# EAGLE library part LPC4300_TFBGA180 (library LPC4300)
TFBGA180 - SOT570-3 TFBGA180: thin fine-pitch ball grid array package; 180 balls body 12 x 12 x 0.8 mm; Solderland 0.4 mm diameter Grid 0.8 x 0.8 mm
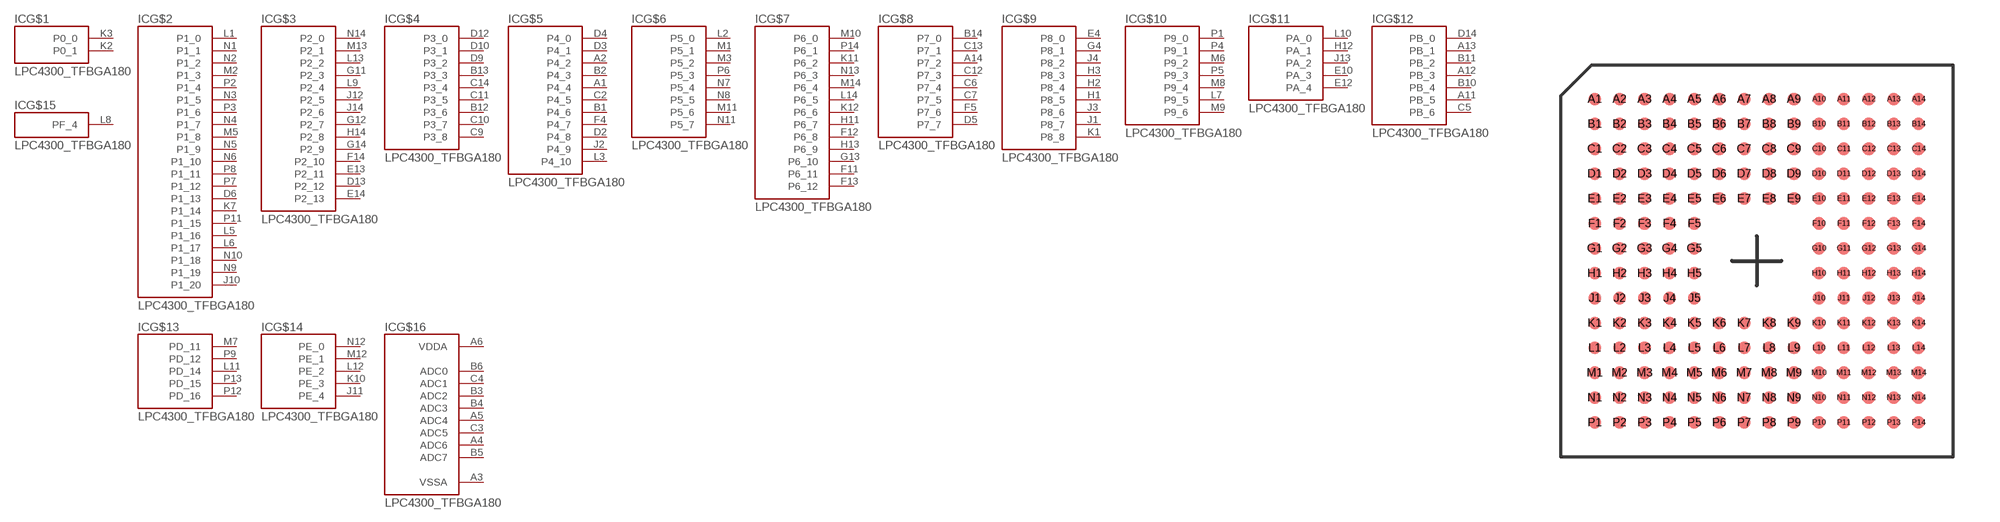
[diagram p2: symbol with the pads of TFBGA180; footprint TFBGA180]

Designator prefix IC; gates G$1=180_1_PORT0 G$2=180_2_PORT1 G$3=180_3_PORT2 G$4=180_4_PORT3 G$5=180_5_PORT4 G$6=180_6_PORT5 G$7=180_7_PORT6 G$8=180_8_PORT7 G$9=180_9_PORT8 G$10=180_10_PORT9 G$11=180_11_PORTA G$12=180_12_PORTB G$13=180_14_PORTD G$14=180_15_PORTE G$15=180_16_PORTF G$16=180_17_ANA G$17=180_18_RTC G$18=180_19_CLK G$19=180_20_DBUG G$20=180_21_I2C G$21=180_22_SUP G$22=180_23_USB

## LPC4300_TFBGA180  [TFBGA180]
A1  G$5:P4_4
A2  G$5:P4_2
A3  G$16:VSSA  sup
A4  G$16:ADC6  in
A5  G$16:ADC4  in
A6  G$16:VDDA  sup
A7  G$17:RTCX2  out
A8  G$17:RTCX1  in
A9  G$17:WAKEUP0  in
A10  G$17:RTC_ALARM  out
A11  G$12:PB_5
A12  G$12:PB_3
A13  G$12:PB_1
A14  G$8:P7_2
B1  G$5:P4_6
B2  G$5:P4_3
B3  G$16:ADC2  in
B4  G$16:ADC3  in
B5  G$16:ADC7  in
B6  G$16:ADC0  in
B7  G$18:!RESET  in
B8  G$17:!SAMPLE  out
B9  G$17:VBAT  pwr
B10  G$12:PB_4
B11  G$12:PB_2
B12  G$4:P3_6
B13  G$4:P3_3
B14  G$8:P7_0
C1  G$18:XTAL1  in
C2  G$5:P4_5
C3  G$16:ADC5  in
C4  G$16:ADC1  in
C5  G$12:PB_6
C6  G$8:P7_4
C7  G$8:P7_5
C8  G$17:WAKEUP1  in
C9  G$4:P3_8
C10  G$4:P3_7
C11  G$4:P3_5
C12  G$8:P7_3
C13  G$8:P7_1
C14  G$4:P3_4
D1  G$18:XTAL2  out
D2  G$5:P4_8
D3  G$5:P4_1
D4  G$5:P4_0
D5  G$8:P7_7
D6  G$2:P1_13
D7  G$21:VSS3  sup
D8  G$21:VDDREG1  sup
D9  G$4:P3_2
D10  G$4:P3_1
D11  G$22:USB1_DP
D12  G$4:P3_0
D13  G$3:P2_12
D14  G$12:PB_0
E1  G$22:USB0_VBUS
E2  G$22:USB0_DP
E3  G$22:USB0_VDDA3V3_DRIVER
E4  G$9:P8_0
E5  G$17:WAKEUP2  in
E6  G$21:VSS4  sup
E7  G$21:VSS5  sup
E8  G$21:VDDREG2  sup
E9  G$21:VSS6  sup
E10  G$11:PA_3
E11  G$22:USB1_DM
E12  G$11:PA_4
E13  G$3:P2_11
E14  G$3:P2_13
F1  G$22:USB0_VSSA_REF
F2  G$22:USB0_DM
F3  G$22:USB0_VDDA3V3
F4  G$5:P4_7
F5  G$8:P7_6
F10  G$21:VSS1  sup
F11  G$7:P6_11
F12  G$7:P6_8
F13  G$7:P6_12
F14  G$3:P2_10
G1  G$22:USB0_RREF
G2  G$22:USB0_ID
G3  G$22:USB0_VSSA_TERM
G4  G$9:P8_1
G5  G$19:TCK
G10  G$21:VSS2  sup
G11  G$3:P2_3
G12  G$3:P2_7
G13  G$7:P6_10
G14  G$3:P2_9
H1  G$9:P8_5
H2  G$9:P8_4
H3  G$9:P8_3
H4  G$19:TDI
H5  G$21:VDDIO1  sup
H10  G$21:VDDIO2  sup
H11  G$7:P6_7
H12  G$11:PA_1
H13  G$7:P6_9
H14  G$3:P2_8
J1  G$9:P8_7
J2  G$5:P4_9
J3  G$9:P8_6
J4  G$9:P8_2
J5  G$19:TDO
J10  G$2:P1_20
J11  G$14:PE_4
J12  G$3:P2_5
J13  G$11:PA_2
J14  G$3:P2_6
K1  G$9:P8_8  sup
K2  G$1:P0_1
K3  G$1:P0_0
K4  G$19:DBGEN  in
K5  G$19:TMS
K6  G$21:VSS7  sup
K7  G$2:P1_14
K8  G$21:VDDIO3  sup
K9  G$21:VSS8  sup
K10  G$14:PE_3
K11  G$7:P6_2
K12  G$7:P6_6
K13  G$20:I2C0_SCL
K14  G$20:I2C0_SDA
L1  G$2:P1_0
L2  G$6:P5_0
L3  G$5:P4_10
L4  G$19:!TRST
L5  G$2:P1_16
L6  G$2:P1_17
L7  G$10:P9_5
L8  G$15:PF_4
L9  G$3:P2_4
L10  G$11:PA_0
L11  G$13:PD_14
L12  G$14:PE_2
L13  G$3:P2_2
L14  G$7:P6_5
M1  G$6:P5_1
M2  G$2:P1_3
M3  G$6:P5_2
M4  G$18:CLK0  out
M5  G$2:P1_8
M6  G$10:P9_2
M7  G$13:PD_11
M8  G$10:P9_4
M9  G$10:P9_6
M10  G$7:P6_0
M11  G$6:P5_6
M12  G$14:PE_1
M13  G$3:P2_1
M14  G$7:P6_4
N1  G$2:P1_1
N2  G$2:P1_2
N3  G$2:P1_5
N4  G$2:P1_7
N5  G$2:P1_9
N6  G$2:P1_10
N7  G$6:P5_4
N8  G$6:P5_5
N9  G$2:P1_19
N10  G$2:P1_18
N11  G$6:P5_7
N12  G$14:PE_0
N13  G$7:P6_3
N14  G$3:P2_0
P1  G$10:P9_0
P2  G$2:P1_4
P3  G$2:P1_6
P4  G$10:P9_1
P5  G$10:P9_3
P6  G$6:P5_3
P7  G$2:P1_12
P8  G$2:P1_11
P9  G$13:PD_12
P10  G$18:CLK2  out
P11  G$2:P1_15
P12  G$13:PD_16
P13  G$13:PD_15
P14  G$7:P6_1

## Footprint TFBGA180 (pad centres in mm)
TFBGA180 - SOT570-3 TFBGA180: thin fine-pitch ball grid array package; 180 balls body 12 x 12 x 0.8 mm; Solderland 0.4 mm diameter Grid 0.8 x 0.8 mm
smd 0.4 x 0.4: A1 -5.2,5.2; A2 -4.4,5.2; A3 -3.6,5.2; A4 -2.8,5.2; A5 -2,5.2; A6 -1.2,5.2; A7 -0.4,5.2; A8 0.4,5.2; A9 1.2,5.2; A10 2,5.2; A11 2.8,5.2; A12 3.6,5.2; A13 4.4,5.2; A14 5.2,5.2; B1 -5.2,4.4; B2 -4.4,4.4; B3 -3.6,4.4; B4 -2.8,4.4; B5 -2,4.4; B6 -1.2,4.4; B7 -0.4,4.4; B8 0.4,4.4; B9 1.2,4.4; B10 2,4.4; B11 2.8,4.4; B12 3.6,4.4; B13 4.4,4.4; B14 5.2,4.4; C1 -5.2,3.6; C2 -4.4,3.6; C3 -3.6,3.6; C4 -2.8,3.6; C5 -2,3.6; C6 -1.2,3.6; C7 -0.4,3.6; C8 0.4,3.6; C9 1.2,3.6; C10 2,3.6; C11 2.8,3.6; C12 3.6,3.6; C13 4.4,3.6; C14 5.2,3.6; D1 -5.2,2.8; D2 -4.4,2.8; D3 -3.6,2.8; D4 -2.8,2.8; D5 -2,2.8; D6 -1.2,2.8; D7 -0.4,2.8; D8 0.4,2.8; D9 1.2,2.8; D10 2,2.8; D11 2.8,2.8; D12 3.6,2.8; D13 4.4,2.8; D14 5.2,2.8; E1 -5.2,2; E2 -4.4,2; E3 -3.6,2; E4 -2.8,2; E5 -2,2; E6 -1.2,2; E7 -0.4,2; E8 0.4,2; E9 1.2,2; E10 2,2; E11 2.8,2; E12 3.6,2; E13 4.4,2; E14 5.2,2; F1 -5.2,1.2; F2 -4.4,1.2; F3 -3.6,1.2; F4 -2.8,1.2; F5 -2,1.2; F10 2,1.2; F11 2.8,1.2; F12 3.6,1.2; F13 4.4,1.2; F14 5.2,1.2; G1 -5.2,0.4; G2 -4.4,0.4; G3 -3.6,0.4; G4 -2.8,0.4; G5 -2,0.4; G10 2,0.4; G11 2.8,0.4; G12 3.6,0.4; G13 4.4,0.4; G14 5.2,0.4; H1 -5.2,-0.4; H2 -4.4,-0.4; H3 -3.6,-0.4; H4 -2.8,-0.4; H5 -2,-0.4; H10 2,-0.4; H11 2.8,-0.4; H12 3.6,-0.4; H13 4.4,-0.4; H14 5.2,-0.4; J1 -5.2,-1.2; J2 -4.4,-1.2; J3 -3.6,-1.2; J4 -2.8,-1.2; J5 -2,-1.2; J10 2,-1.2; J11 2.8,-1.2; J12 3.6,-1.2; J13 4.4,-1.2; J14 5.2,-1.2; K1 -5.2,-2; K2 -4.4,-2; K3 -3.6,-2; K4 -2.8,-2; K5 -2,-2; K6 -1.2,-2; K7 -0.4,-2; K8 0.4,-2; K9 1.2,-2; K10 2,-2; K11 2.8,-2; K12 3.6,-2; K13 4.4,-2; K14 5.2,-2; L1 -5.2,-2.8; L2 -4.4,-2.8; L3 -3.6,-2.8; L4 -2.8,-2.8; L5 -2,-2.8; L6 -1.2,-2.8; L7 -0.4,-2.8; L8 0.4,-2.8; L9 1.2,-2.8; L10 2,-2.8; L11 2.8,-2.8; L12 3.6,-2.8; L13 4.4,-2.8; L14 5.2,-2.8; M1 -5.2,-3.6; M2 -4.4,-3.6; M3 -3.6,-3.6; M4 -2.8,-3.6; M5 -2,-3.6; M6 -1.2,-3.6; M7 -0.4,-3.6; M8 0.4,-3.6; M9 1.2,-3.6; M10 2,-3.6; M11 2.8,-3.6; M12 3.6,-3.6; M13 4.4,-3.6; M14 5.2,-3.6; N1 -5.2,-4.4; N2 -4.4,-4.4; N3 -3.6,-4.4; N4 -2.8,-4.4; N5 -2,-4.4; N6 -1.2,-4.4; N7 -0.4,-4.4; N8 0.4,-4.4; N9 1.2,-4.4; N10 2,-4.4; N11 2.8,-4.4; N12 3.6,-4.4; N13 4.4,-4.4; N14 5.2,-4.4; P1 -5.2,-5.2; P2 -4.4,-5.2; P3 -3.6,-5.2; P4 -2.8,-5.2; P5 -2,-5.2; P6 -1.2,-5.2; P7 -0.4,-5.2; P8 0.4,-5.2; P9 1.2,-5.2; P10 2,-5.2; P11 2.8,-5.2; P12 3.6,-5.2; P13 4.4,-5.2; P14 5.2,-5.2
